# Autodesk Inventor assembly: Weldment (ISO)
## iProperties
Length Units: 11269
Angle Units: 11283
Time Units: 11279
Mass Units: 11290
Length Display Precision: 3
Angle Display Precision: 2
Part Number: Weldment (ISO)
Document SubType Name: Weldment
Created: 2002-06
Designer: smithga
Part Number: Ens_flasque_palier
Created: 2008-02
Designer: Pascal
Material: Aluminum soudé-6061
Control State: 0
Master: False
Shininess: 64.0
Angle Units: 11279
Time Units: 11290
Mass Units: 11283
Compacted: True
DESIGNATION: Ensemble flasque palier
OBSERVATIONS: Ø715 ep. 20
Density: 0.0
Volumn: 0.0
Area: 0.0
PropertySet Name: Model Information
Author: Pascal
